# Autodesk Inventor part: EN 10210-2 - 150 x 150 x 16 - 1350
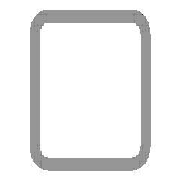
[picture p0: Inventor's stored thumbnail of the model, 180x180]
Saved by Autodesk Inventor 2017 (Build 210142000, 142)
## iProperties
Created: 2017-11
Part Number: EN 10210-2 - 150 x 150 x 16 - 1350
Material: Steel, Mild
Description: Tube
Document SubType Name: Modeling
Standard: DIN
Designer: iusti
Standard Revision: 2006-07
Standards Organization: DIN
Language: en-US
Size Designation: 150 x 150 x 16
Categories: <MemberInstance><Categories><Category DisplayName="Structural Shapes" InternalName="089c4875-fa83-4c05-b084-43b9cc11f5ed" Mnemonic="GRDR"><CategoryParameter Dis
Stock Number: 150 x 150 x 16
Mass: 87973.1 g
Surface Area: 13710.9 cm^2
Volume: 11206.8 cm^3
Density: 7.85 g/cm^3
Appearance: Semi-Polished
_CCFamilyMember: 70
_CCFamilyDisplayName: DIN EN 10210-2 (Square) - Tube — Sizes in parentheses have been withdrawn
_FrameMemberDoc: Frame Member File
_Version: 15.0.0
_GetPNFromCC: 1
IsCustomPart: 1
Author: iusti
G_L: 1350.000 mm
G_W: 150.000 mm
G_H: 150.000 mm
+4E384797-F5C2-4545-984B-C3C24EE06726+CUTDETAIL1: Cut
+B72626A9-E0F7-499A-B548-87DD43E619E9+CUTDETAIL2: Cut
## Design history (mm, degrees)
node "Start plane"
node "End plane"
sketch "Sketch"
  geometry: L1 (-75, -51)-(-75, 51); L2 (-51, 75)-(51, 75); L3 (75, 51)-(75, -51); L4 (51, -75)-(-51, -75); L5 (-43, 59)-(43, 59); L6 (59, 43)-(59, -43); L7 (43, -59)-(-43, -59); L8 (-59, -43)-(-59, 43); L9 (0, 111.959)-(0, -111.959) reference; L10 (-111.959, 0)-(111.959, 0) reference; A1 r 24 centre (-51, -51) between (-75, -51) and (-51, -75); A2 r 24 centre (-51, 51) between (-51, 75) and (-75, 51); A3 r 24 centre (51, 51) between (75, 51) and (51, 75); A4 r 24 centre (51, -51) between (51, -75) and (75, -51); A5 r 16 centre (-43, -43) between (-59, -43) and (-43, -59); A6 r 16 centre (-43, 43) between (-43, 59) and (-59, 43); A7 r 16 centre (43, 43) between (59, 43) and (43, 59); A8 r 16 centre (43, -43) between (43, -59) and (59, -43)
  constraints: 16 end point, 16 point on circle, 16 tangent, 8 centre point, 6 equal radius, 4 parallel, 2 perpendicular, 2 other
  dimensions: "d7" = 24 radius of A1 (= G_IR); "d10" = 150 distance between parallel lines of L2 L4 (= G_H); "d11" = 150 distance between parallel lines of L1 L3 (= G_W); "d12" = 16 distance between parallel lines of L3 L6 (= G_T); "d15" = 75 distance between parallel lines of L2 L10 (= 0.5 x d10); "d16" = 75 distance between parallel lines of L9 L3 (= 0.5 x d11); "d19" = 16 radius of A5 (= G_T); "d20" = 16 distance between parallel lines of L4 L7 (= G_T)
extrude "Body" new body sketch "Sketch" stored distance "d3" = 1350 (= G_L); taper "d4" = 0 deg
node "Driven Length"
  sketch "Sketch3"
    geometry: L1 (0, 0)-(10, 0) reference
    constraints: 2 end point, 1 horizontal
  workplane "Work Plane3"
  sketch "Sketch4"
    geometry: L1 (-2, 75)-(12, 75) reference; L2 (-2, 1425)-(12, 1425) reference
    dimensions: "d18" = 1350 distance between parallel lines of L1 L2 (derived)
workplane "Work Plane4"
split "Split1"
workplane "Work Plane5"
split "Split2"
body "Solid1"
other parameters: "G_W" = 150 [user parameter; used in 1 equation term], "G_H" = 150 [user parameter; used in 1 equation term], "G_T" = 16 [user parameter; used in 3 equation terms], "G_IR" = 24 [user parameter; used in 1 equation term], "G_L" = 1350 (= d18) [user parameter; used in 1 equation term], "G_OFFSET_START" = -75 [user parameter; used in 1 equation term], "G_OFFSET_END" = -75 [user parameter; used in 1 equation term], "d13" = 75 (= -G_OFFSET_START), "d14" = 1425 (= G_OFFSET_END + B_L), "d17" = 90 deg
